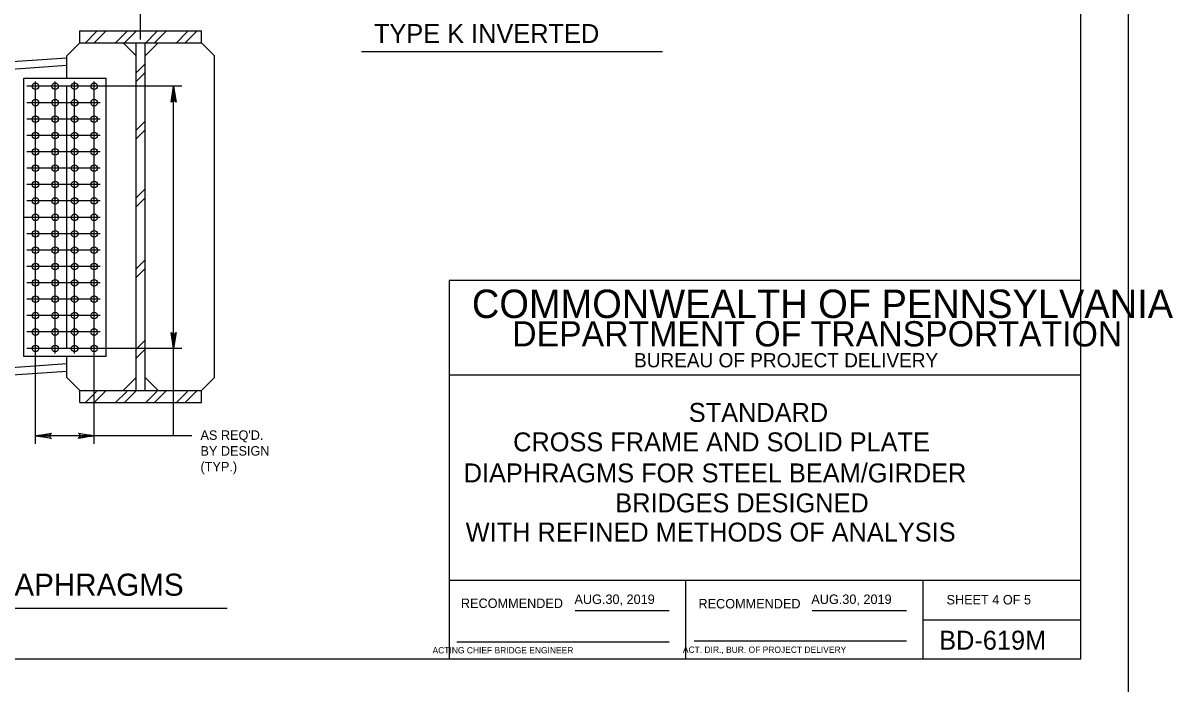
# Model space of a CAD drawing. Extents: x 634656 to 641360, y 298715 to 301183.
# Drawn here: x 638707.5 to 639071.7, y 299920.5 to 300129.6 of the extents above; entities that cross this region are included whole.
import ezdxf

# ---------------------------------------------------------------- set-up
doc = ezdxf.new("R2010")
doc.units = 0
for name, color, linetype in [('1', 7, 'Continuous'), ('2', 7, 'Continuous'), ('PLT-BNDY', 7, 'Continuous')]:
    doc.layers.add(name, color=color, linetype=linetype)

msp = doc.modelspace()

# ---------------------------------------------------------------- linework, layer by layer
at = {"layer": '1'}
for p, q in [((638744.79, 300124.32), (638744.79, 300138.32)), ((638725.5, 300127.1), (638764.09, 300127.1)), ((638725.5, 300123.3), (638725.5, 300127.1)), ((638730.86, 300126.84), (638727.24, 300123.21)), ((638733.9, 300127.1), (638730.11, 300123.3)), ((638740.39, 300126.84), (638736.77, 300123.21)), ((638743.44, 300127.1), (638739.64, 300123.3)), ((638749.92, 300126.84), (638746.3, 300123.21)), ((638752.97, 300127.1), (638749.17, 300123.3)), ((638759.68, 300126.84), (638756.06, 300123.21)), ((638762.73, 300127.1), (638758.93, 300123.3)), ((638764.09, 300123.3), (638764.09, 300127.1)), ((638721.39, 300119.19), (638725.5, 300123.3)), ((638725.5, 300123.3), (638764.09, 300123.3)), ((638743.37, 300119.19), (638739.26, 300123.3)), ((638743.37, 300013.14), (638743.37, 300123.3)), ((638746.22, 300013.14), (638746.22, 300123.3)), ((638746.22, 300119.19), (638750.33, 300123.3)), ((638768.2, 300119.19), (638764.09, 300123.3)), ((638602.18, 300110.19), (638721.39, 300118.57)), ((638721.39, 300112.1), (638721.39, 300119.19)), ((638746.22, 300116.62), (638743.37, 300113.77)), ((638768.2, 300017.25), (638768.2, 300119.19)), ((638602.18, 300107.81), (638721.39, 300116.19)), ((638746.22, 300113.84), (638743.37, 300110.99)), ((638707.78, 300112.1), (638733.84, 300112.1)), ((638707.78, 300023.9), (638707.78, 300112.1)), ((638757.85, 300109.51), (638708.72, 300109.51)), ((638711.53, 299996.29), (638711.53, 300111.05)), ((638717.72, 300024.82), (638717.72, 300111.05)), ((638721.39, 300026.4), (638721.39, 300109.51)), ((638723.9, 300024.82), (638723.9, 300111.05)), ((638730.09, 299996.29), (638730.09, 300111.05)), ((638733.84, 300023.9), (638733.84, 300112.1)), ((638755.22, 299998.78), (638755.22, 300109.51)), ((638731.96, 300104.32), (638708.72, 300104.32)), ((638731.96, 300099.13), (638708.72, 300099.13)), ((638746.22, 300098.45), (638743.37, 300095.6)), ((638746.22, 300095.67), (638743.37, 300092.82)), ((638731.96, 300093.94), (638708.72, 300093.94)), ((638731.96, 300088.76), (638708.72, 300088.76)), ((638731.96, 300083.57), (638708.72, 300083.57)), ((638731.96, 300078.38), (638708.72, 300078.38)), ((638746.22, 300077), (638743.37, 300074.14)), ((638731.96, 300073.19), (638708.72, 300073.19)), ((638746.22, 300074.22), (638743.37, 300071.37)), ((638731.96, 300068), (638707.78, 300068)), ((638731.96, 300062.81), (638708.72, 300062.81)), ((638731.96, 300057.62), (638708.72, 300057.62)), ((638746.22, 300054.53), (638743.37, 300051.68)), ((638731.96, 300052.44), (638708.72, 300052.44)), ((638746.22, 300051.76), (638743.37, 300048.9)), ((638731.96, 300047.25), (638708.72, 300047.25)), ((638731.96, 300042.06), (638708.72, 300042.06)), ((638731.96, 300036.87), (638708.72, 300036.87)), ((638731.96, 300031.68), (638708.72, 300031.68)), ((638746.22, 300029.04), (638743.37, 300026.19)), ((638757.85, 300026.49), (638708.72, 300026.49)), ((638746.22, 300026.26), (638743.37, 300023.41)), ((638603.33, 300013.4), (638721.39, 300021.7)), ((638733.84, 300023.9), (638707.78, 300023.9)), ((638721.39, 300017.25), (638721.39, 300023.9)), ((638603.33, 300011.02), (638721.39, 300019.31)), ((638721.39, 300017.25), (638725.5, 300013.14)), ((638743.37, 300017.25), (638739.26, 300013.14)), ((638746.22, 300017.25), (638750.33, 300013.14)), ((638768.2, 300017.25), (638764.09, 300013.14)), ((638725.5, 300013.14), (638764.09, 300013.14)), ((638725.5, 300009.34), (638725.5, 300013.14)), ((638730.86, 300012.87), (638727.24, 300009.25)), ((638733.9, 300013.14), (638730.11, 300009.34)), ((638740.39, 300012.87), (638736.77, 300009.25)), ((638743.44, 300013.14), (638739.64, 300009.34)), ((638749.92, 300012.87), (638746.3, 300009.25)), ((638752.97, 300013.14), (638749.17, 300009.34)), ((638759.68, 300012.87), (638756.06, 300009.25)), ((638762.73, 300013.14), (638758.93, 300009.34)), ((638764.09, 300009.34), (638764.09, 300013.14)), ((638725.5, 300009.34), (638764.09, 300009.34)), ((638730.09, 299998.78), (638711.53, 299998.78)), ((638761.04, 299998.78), (638730.09, 299998.78))]:
    msp.add_line(p, q, dxfattribs=at)
for points in [[(638754.62, 300104.74), (638754.96, 300104.92), (638755.22, 300109.51), (638754.62, 300104.74), (638754.41, 300104.5), (638755.22, 300109.51), (638755.44, 300104.92), (638755.79, 300104.76), (638755.22, 300109.51), (638756.01, 300104.5), (638755.79, 300104.76)], [(638755.82, 300031.26), (638755.47, 300031.08), (638755.22, 300026.49), (638755.82, 300031.26), (638756.03, 300031.51), (638755.22, 300026.49), (638754.99, 300031.08), (638754.65, 300031.25), (638755.22, 300026.49), (638754.42, 300031.51), (638754.65, 300031.25)], [(638716.3, 299998.18), (638716.12, 299998.53), (638711.53, 299998.78), (638716.3, 299998.18), (638716.54, 299997.98), (638711.53, 299998.78), (638716.12, 299999.01), (638716.28, 299999.35), (638711.53, 299998.78), (638716.54, 299999.58), (638716.28, 299999.35)], [(638725.32, 299999.38), (638725.5, 299999.04), (638730.09, 299998.78), (638725.32, 299999.38), (638725.08, 299999.59), (638730.09, 299998.78), (638725.5, 299998.56), (638725.33, 299998.21), (638730.09, 299998.78), (638725.08, 299997.99), (638725.33, 299998.21)]]:
    msp.add_lwpolyline(points, dxfattribs=at)
for centre in [(638711.53, 300109.51), (638717.72, 300109.51), (638723.9, 300109.51), (638730.09, 300109.51), (638711.53, 300104.32), (638717.72, 300104.32), (638723.9, 300104.32), (638730.09, 300104.32), (638711.53, 300099.13), (638717.72, 300099.13), (638723.9, 300099.13), (638730.09, 300099.13), (638711.53, 300093.94), (638717.72, 300093.94), (638723.9, 300093.94), (638730.09, 300093.94), (638711.53, 300088.76), (638717.72, 300088.76), (638723.9, 300088.76), (638730.09, 300088.76), (638711.53, 300083.57), (638717.72, 300083.57), (638723.9, 300083.57), (638730.09, 300083.57), (638711.53, 300078.38), (638717.72, 300078.38), (638723.9, 300078.38), (638730.09, 300078.38), (638711.53, 300073.19), (638717.72, 300073.19), (638723.9, 300073.19), (638730.09, 300073.19), (638711.53, 300068), (638717.72, 300068), (638723.9, 300068), (638730.09, 300068), (638711.53, 300062.81), (638717.72, 300062.81), (638723.9, 300062.81), (638730.09, 300062.81), (638711.53, 300057.62), (638717.72, 300057.62), (638723.9, 300057.62), (638730.09, 300057.62), (638711.53, 300052.44), (638717.72, 300052.44), (638723.9, 300052.44), (638730.09, 300052.44), (638711.53, 300047.25), (638717.72, 300047.25), (638723.9, 300047.25), (638730.09, 300047.25), (638711.53, 300042.06), (638717.72, 300042.06), (638723.9, 300042.06), (638730.09, 300042.06), (638711.53, 300036.87), (638717.72, 300036.87), (638723.9, 300036.87), (638730.09, 300036.87), (638711.53, 300031.68), (638717.72, 300031.68), (638723.9, 300031.68), (638730.09, 300031.68), (638711.53, 300026.49), (638717.72, 300026.49), (638723.9, 300026.49), (638730.09, 300026.49)]:
    msp.add_circle(centre, 1.04, dxfattribs=at)
at = {"layer": '2'}
for p, q in [((639042.43, 299927.99), (639042.43, 300491.99)), ((638910.02, 300120.45), (638814.75, 300120.45)), ((638842.43, 300047.99), (638842.43, 299927.99)), ((639042.43, 300047.99), (638842.43, 300047.99)), ((639042.43, 300017.99), (638842.43, 300017.99)), ((639042.43, 299952.99), (638842.43, 299952.99)), ((638917.43, 299927.99), (638917.43, 299952.99)), ((638992.43, 299952.99), (638992.43, 299927.99)), ((638668.48, 299944.24), (638772.16, 299944.24)), ((638882.39, 299943.49), (638912.16, 299943.49)), ((638957.39, 299943.49), (638987.3, 299943.49)), ((638992.43, 299940.49), (639042.43, 299940.49)), ((638844.93, 299933.49), (638912.16, 299933.49)), ((638920.05, 299933.86), (638987.3, 299933.86)), ((639042.43, 299927.99), (638256.43, 299927.99))]:
    msp.add_line(p, q, dxfattribs=at)
at = {"layer": 'PLT-BNDY'}
msp.add_lwpolyline([(638216.43, 300506.99), (639057.43, 300506.99), (639057.43, 299912.99), (638216.43, 299912.99)], close=True, dxfattribs=at)

# ---------------------------------------------------------------- texts
at = {"layer": '1'}
for s, height, p in [("AS REQ'D.", 3, (638763.74, 299997.52)), ('BY DESIGN', 3, (638763.74, 299992.52)), ('(TYP.)', 3, (638763.74, 299987.52)), ('AUG.30, 2019', 2.9999, (638882.15, 299945.52)), ('AUG.30, 2019', 2.9999, (638957.15, 299945.52))]:
    msp.add_text(s, height=height, dxfattribs=at).set_placement(p)
at = {"layer": '2'}
for s, height, p in [('TYPE K INVERTED', 6, (638818.66, 300123.23)), ('COMMONWEALTH OF PENNSYLVANIA', 9, (638849.68, 300036.11)), ('DEPARTMENT OF TRANSPORTATION', 8.0002, (638862.43, 300027.11)), ('BUREAU OF PROJECT DELIVERY', 4.5, (638901.02, 300020.49)), ('STANDARD', 6, (638918.35, 300003.2)), ('CROSS FRAME AND SOLID PLATE', 6, (638862.74, 299993.87)), ('DIAPHRAGMS FOR STEEL BEAM/GIRDER', 6, (638847.08, 299984.04)), ('BRIDGES DESIGNED', 6, (638895.08, 299974.55)), ('WITH REFINED METHODS OF ANALYSIS', 6, (638847.71, 299965.29)), ('END DIAPHRAGMS', 7, (638673.1, 299948.13)), ('RECOMMENDED', 3, (638846.2, 299944.24)), ('RECOMMENDED', 3, (638921.42, 299944.11)), ('SHEET 4 OF 5', 3, (638999.96, 299945.38)), ('BD-619M', 6, (638997.63, 299931.05)), ('       ACTING CHIEF BRIDGE ENGINEER', 2.0002, (638832.02, 299929.86)), ('   ACT. DIR., BUR. OF PROJECT DELIVERY', 2.0002, (638914.25, 299930.04))]:
    msp.add_text(s, height=height, dxfattribs=at).set_placement(p)

doc.saveas('drawing.dxf')
